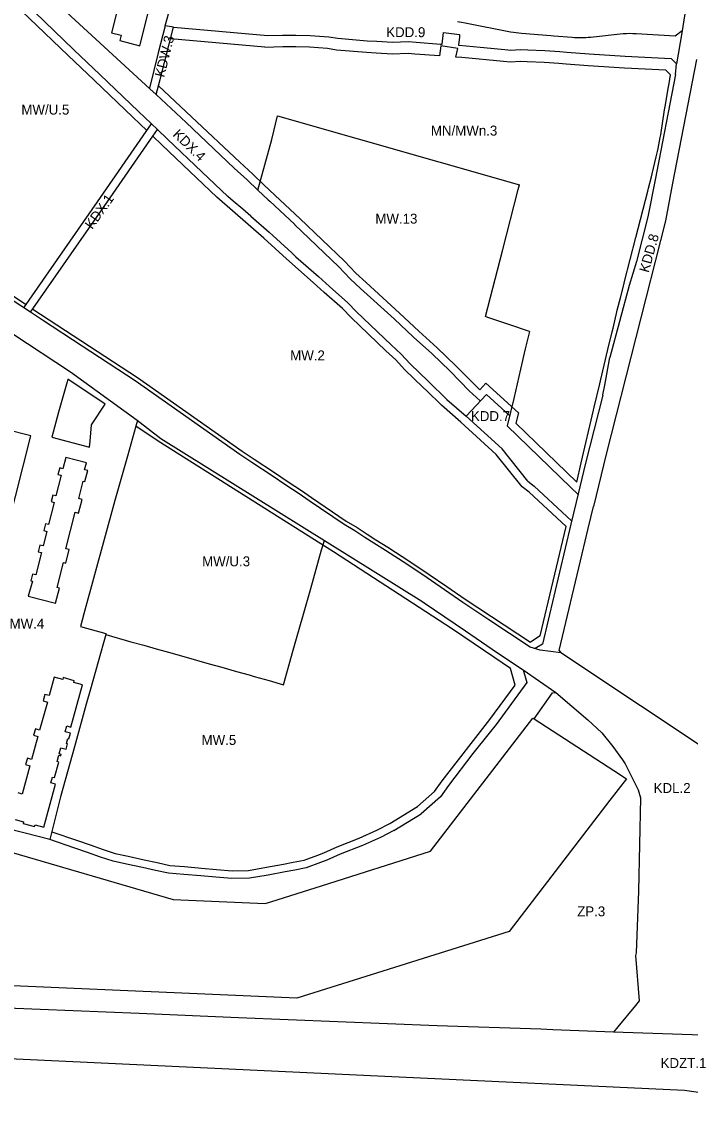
# Model space of a CAD drawing. Extents: x 7427060 to 7429122, y 5545301 to 5546237.
# Drawn here: x 7427447 to 7427783, y 5545402 to 5545952 of the extents above; entities that cross this region are included whole.
import ezdxf

# ---------------------------------------------------------------- set-up
doc = ezdxf.new("R2010")
doc.units = 0
for name, color, linetype in [('LIN_Linia Zabudowy Nieprzekraczalna', 7, 'Continuous'), ('LIN_Linia Zabudowy Obowiązujaca', 7, 'Continuous'), ('LIN_Linie Rozgraniczajace', 7, 'Continuous'), ('TXT_Oznaczenia Przeznaczenia', 7, 'Continuous')]:
    doc.layers.add(name, color=color, linetype=linetype)

msp = doc.modelspace()

# ---------------------------------------------------------------- linework, layer by layer
at = {"layer": 'LIN_Linia Zabudowy Nieprzekraczalna'}
for p, q in [((7427515.49, 5545919.37), (7427532.17, 5545903.75)), ((7427532.17, 5545903.75), (7427556.34, 5545880.88)), ((7427556.34, 5545880.88), (7427562.91, 5545874.92)), ((7427562.91, 5545874.92), (7427568.26, 5545869.74)), ((7427568.26, 5545869.74), (7427574.2, 5545864.16)), ((7427574.2, 5545864.16), (7427586.61, 5545852.55)), ((7427586.61, 5545852.55), (7427609.05, 5545831.07)), ((7427609.05, 5545831.07), (7427614.75, 5545825.05)), ((7427614.75, 5545825.05), (7427619.94, 5545820.27)), ((7427619.94, 5545820.27), (7427636.75, 5545804.98)), ((7427608.08, 5545807.21), (7427598.93, 5545815.39)), ((7427612.39, 5545802.7), (7427608.08, 5545807.21)), ((7427629.84, 5545786.01), (7427612.39, 5545802.7)), ((7427636.75, 5545804.98), (7427646.54, 5545795.79)), ((7427646.54, 5545795.79), (7427655.77, 5545787.49)), ((7427634.87, 5545781.46), (7427629.84, 5545786.01)), ((7427655.77, 5545787.49), (7427665.1, 5545778.47)), ((7427639.3, 5545776.6), (7427634.87, 5545781.46)), ((7427648.65, 5545767.57), (7427639.3, 5545776.6)), ((7427665.1, 5545778.47), (7427677.17, 5545766.24)), ((7427469.81, 5545771.76), (7427469.43, 5545770.37)), ((7427488.62, 5545759.04), (7427469.81, 5545771.76)), ((7427677.17, 5545766.24), (7427680.32, 5545769.63)), ((7427680.32, 5545769.63), (7427696.63, 5545754.74)), ((7427650.32, 5545765.95), (7427648.65, 5545767.57)), ((7427728.18, 5545729.5), (7427734.47, 5545756.06)), ((7427695.36, 5545749.49), (7427726.04, 5545719.83)), ((7427698.51, 5545717.41), (7427685.46, 5545733.8)), ((7427726.04, 5545719.83), (7427728.18, 5545729.5)), ((7427580.71, 5545720.05), (7427587.45, 5545715.57)), ((7427587.45, 5545715.57), (7427592.52, 5545712.1)), ((7427592.52, 5545712.1), (7427610, 5545700.26)), ((7427610, 5545700.26), (7427615.41, 5545696.96)), ((7427615.41, 5545696.96), (7427620.51, 5545693.64)), ((7427620.51, 5545693.64), (7427624.94, 5545690.74)), ((7427624.94, 5545690.74), (7427630.88, 5545687.17)), ((7427630.88, 5545687.17), (7427642.06, 5545679.91)), ((7427642.06, 5545679.91), (7427651.77, 5545673.3)), ((7427651.77, 5545673.3), (7427660.6, 5545667.34)), ((7427660.6, 5545667.34), (7427669.87, 5545660.87)), ((7427669.87, 5545660.87), (7427702.66, 5545639.22)), ((7427707.61, 5545642.4), (7427702.66, 5545639.22))]:
    msp.add_line(p, q, dxfattribs=at)
for points in [[(7427509.67, 5545896.86), (7427502.61, 5545903.62), (7427483.14, 5545922.22), (7427470.05, 5545934.63), (7427450.43, 5545953.5), (7427437, 5545966.33), (7427424.67, 5545986.01), (7427416.22, 5545999.42)], [(7427569.03, 5545938.78), (7427521.48, 5545943.06)], [(7427656.98, 5545934.44), (7427644.55, 5545935.32), (7427641.1, 5545935.72), (7427633.25, 5545935.32), (7427625.1, 5545935.81), (7427620.13, 5545936.08), (7427605.11, 5545937.4), (7427600.49, 5545938.09), (7427591.51, 5545938.78), (7427584.53, 5545938.94), (7427581.53, 5545938.93), (7427578.01, 5545938.93), (7427568.99, 5545938.63)], [(7427665.18, 5545933.85), (7427666.11, 5545938.13), (7427657.56, 5545939.58), (7427656.98, 5545934.44)], [(7427668.16, 5545933.64), (7427665.18, 5545933.85)], [(7427773.16, 5545924.96), (7427770.94, 5545927.19), (7427750, 5545928.3), (7427731.84, 5545929.51), (7427720.66, 5545930.34), (7427717.01, 5545930.61), (7427709.62, 5545931.14), (7427701.1, 5545931.43), (7427697.58, 5545931.59), (7427692.73, 5545931.25), (7427689.15, 5545931.65), (7427668.16, 5545933.64)], [(7427734.47, 5545756.06), (7427734.8, 5545757.52), (7427737.6, 5545769.35), (7427738, 5545770.91), (7427741.72, 5545786.63), (7427742.05, 5545788.11), (7427743.47, 5545794.03), (7427743.87, 5545795.59), (7427744.27, 5545797.34), (7427744.65, 5545798.88), (7427746.04, 5545804.75), (7427746.44, 5545806.35), (7427747.96, 5545812.58), (7427749.64, 5545819.22), (7427750.07, 5545820.79), (7427755.78, 5545843.02), (7427761.75, 5545866.33), (7427762.15, 5545867.85), (7427763.57, 5545873.52), (7427764.01, 5545875.13), (7427766.06, 5545883.58), (7427766.65, 5545886.37), (7427766.96, 5545887.85), (7427767.96, 5545893.3), (7427768.27, 5545894.73), (7427770.27, 5545907.32), (7427770.56, 5545908.99), (7427772.19, 5545918.91), (7427772.46, 5545920.46), (7427773.16, 5545924.96)], [(7427544.8, 5545863.39), (7427534.59, 5545873.11), (7427517.24, 5545889.61), (7427512.59, 5545894.06)], [(7427352.42, 5545872.18), (7427414.39, 5545831.76), (7427422.77, 5545826.42), (7427448.9, 5545809.21)], [(7427598.93, 5545815.39), (7427593.39, 5545820.35), (7427579.84, 5545832.24), (7427568.5, 5545842.71), (7427544.8, 5545863.39)], [(7427452.24, 5545807), (7427504.85, 5545772.52), (7427557.56, 5545735.42), (7427563.62, 5545731.4), (7427573.79, 5545724.65), (7427580.71, 5545720.05)], [(7427469.43, 5545770.37), (7427465.2, 5545755.15), (7427461.71, 5545742.41), (7427480.77, 5545737.44), (7427481.01, 5545740.42), (7427481.79, 5545748.67), (7427488.62, 5545759.04)], [(7427685.46, 5545733.8), (7427667.67, 5545750.03), (7427657.93, 5545758.56), (7427650.32, 5545765.95)], [(7427696.63, 5545754.74), (7427695.36, 5545749.49)], [(7427653.4, 5545652.36), (7427603.49, 5545684.74), (7427515.39, 5545740.53), (7427504.08, 5545747.95)], [(7427720.68, 5545697.46), (7427702.08, 5545714.73), (7427698.51, 5545717.41)], [(7427707.61, 5545642.4), (7427720.68, 5545697.46)], [(7427692.68, 5545626.03), (7427684.35, 5545631.78), (7427663.51, 5545645.76), (7427653.4, 5545652.36)], [(7427695.01, 5545617.71), (7427692.68, 5545626.03)], [(7427461.71, 5545543.77), (7427474.68, 5545539.42), (7427481.04, 5545537.2), (7427487.62, 5545534.89), (7427493.67, 5545532.9), (7427500.14, 5545531.5), (7427508.25, 5545529.73), (7427514.75, 5545528.31), (7427521.19, 5545526.91), (7427528.53, 5545526.29), (7427537.08, 5545525.55), (7427544.62, 5545524.91), (7427552.54, 5545524.22), (7427560.83, 5545524.4), (7427569.91, 5545525.96), (7427578.47, 5545527.51), (7427583.35, 5545528.47), (7427588.76, 5545529.52), (7427595.65, 5545532.04), (7427598.64, 5545533.14), (7427605.4, 5545536.22), (7427616.54, 5545540.62), (7427625.42, 5545544.58), (7427631.91, 5545547.97), (7427645.85, 5545556.53), (7427654.35, 5545564.14), (7427658.21, 5545569.53), (7427682.27, 5545600.28), (7427695.01, 5545617.71)]]:
    msp.add_lwpolyline(points, dxfattribs=at)
at = {"layer": 'LIN_Linia Zabudowy Obowiązujaca'}
for points in [[(7427508.23, 5546015.36), (7427508.7, 5546013.27), (7427505.68, 5546001.27), (7427491.76, 5545946.04), (7427496.67, 5545944.79), (7427496.01, 5545942.12), (7427506.07, 5545939.57), (7427510.61, 5545957.48), (7427509.6, 5545957.75), (7427510.26, 5545960.36), (7427510.96, 5545963.11), (7427511.97, 5545962.85), (7427516.31, 5545980.2), (7427517.92, 5545986.57), (7427519.54, 5545992.99), (7427520.67, 5545997.46), (7427520.82, 5545997.96), (7427519.77, 5545998.23), (7427520.45, 5546000.84), (7427521.19, 5546003.58), (7427522.17, 5546003.34), (7427524.44, 5546012.33), (7427515.23, 5546014.57), (7427514.52, 5546016.56)], [(7427443.37, 5545550), (7427447.6, 5545548.85), (7427447.37, 5545548), (7427453.07, 5545546.44), (7427453.32, 5545547.34), (7427457.69, 5545546.15), (7427463.6, 5545567.77), (7427461.28, 5545568.4), (7427462.1, 5545571.39), (7427463.2, 5545571.09), (7427465.35, 5545578.95), (7427464.48, 5545579.19), (7427465.34, 5545582.32), (7427466.3, 5545582.06), (7427466.49, 5545582.73), (7427465.52, 5545583), (7427466.37, 5545586.08), (7427468.98, 5545585.37), (7427469.72, 5545588.07), (7427469.14, 5545588.23), (7427469.82, 5545590.74), (7427470.37, 5545590.59), (7427471.14, 5545593.4), (7427468.54, 5545594.11), (7427469.35, 5545597.08), (7427471.38, 5545596.53), (7427477.2, 5545617.83), (7427472.86, 5545619.01), (7427473.09, 5545619.88), (7427467.5, 5545621.41), (7427467.26, 5545620.54), (7427462.97, 5545621.71), (7427460.41, 5545612.35), (7427458.29, 5545612.93), (7427457.41, 5545609.72), (7427459.53, 5545609.14), (7427455.66, 5545594.98), (7427453.48, 5545595.57), (7427452.62, 5545592.43), (7427454.8, 5545591.83), (7427451.63, 5545580.21), (7427449.48, 5545580.8), (7427448.61, 5545577.64), (7427450.76, 5545577.05), (7427446.87, 5545562.79), (7427444.76, 5545563.37)]]:
    msp.add_lwpolyline(points, dxfattribs=at)
for points in [[(7427418.42, 5545670.22), (7427431.7, 5545666.82), (7427451.28, 5545743.12), (7427438.02, 5545746.53)], [(7427479.19, 5545729.55), (7427468.82, 5545732.19), (7427467.31, 5545726.6), (7427465.74, 5545727.02), (7427464.85, 5545723.71), (7427466.48, 5545723.29), (7427463.88, 5545712.96), (7427462.24, 5545713.33), (7427461.38, 5545710.04), (7427463.02, 5545709.65), (7427460.14, 5545698.45), (7427458.56, 5545698.81), (7427457.7, 5545695.52), (7427459.28, 5545695.07), (7427457.39, 5545687.7), (7427455.82, 5545688.05), (7427454.95, 5545684.76), (7427456.52, 5545684.35), (7427453.73, 5545673.13), (7427452.13, 5545673.51), (7427451.25, 5545670.23), (7427451.98, 5545670.03), (7427449.95, 5545662.45), (7427463.71, 5545658.93), (7427465.63, 5545666.42), (7427464.46, 5545666.72), (7427467.66, 5545679.31), (7427468.83, 5545679.01), (7427470.58, 5545685.89), (7427468.83, 5545686.34), (7427473.52, 5545704.73), (7427475.26, 5545704.29), (7427477.02, 5545711.14), (7427475.3, 5545711.58), (7427477.54, 5545720.41), (7427478.4, 5545720.2), (7427479.85, 5545725.67), (7427478.31, 5545726.02)]]:
    msp.add_lwpolyline(points, close=True, dxfattribs=at)
at = {"layer": 'LIN_Linie Rozgraniczajace'}
for p, q in [((7427518.85, 5545949.52), (7427522.48, 5545962.91)), ((7427522.97, 5545948.95), (7427518.85, 5545949.52)), ((7427778.85, 5545946.12), (7427776.24, 5545930.38)), ((7427775.67, 5545925.14), (7427776.24, 5545930.38)), ((7427509.3, 5545896.34), (7427511.98, 5545900.19)), ((7427484.77, 5545860.95), (7427509.3, 5545896.34)), ((7427447.76, 5545807.56), (7427484.77, 5545860.95)), ((7427670.34, 5545753.01), (7427680.55, 5545764)), ((7427701.32, 5545720.3), (7427688.39, 5545736.54)), ((7427723.04, 5545717.16), (7427726.65, 5545713.68)), ((7427597.58, 5545685.72), (7427599.05, 5545690.47)), ((7427708.7, 5545638.35), (7427705.12, 5545636.05)), ((7427717.19, 5545635.14), (7427718, 5545633.88)), ((7427742.75, 5545559.75), (7427691.96, 5545493.61)), ((7427633.88, 5545544.49), (7427647.78, 5545552.9)), ((7427422.46, 5545538.97), (7427522.78, 5545509.77)), ((7427585.14, 5545459.97), (7427206.59, 5545476.7)), ((7427746.69, 5545445.54), (7427744.57, 5545442.93))]:
    msp.add_line(p, q, dxfattribs=at)
for points in [[(7427565.5, 5545866.85), (7427560.18, 5545872), (7427553.62, 5545877.94), (7427529.43, 5545900.84), (7427514.37, 5545914.94), (7427511.16, 5545917.88), (7427469.3, 5545956.34), (7427456.33, 5545968.26), (7427443.51, 5545981.95), (7427427.27, 5546009.82)], [(7427550.41, 5545863.58), (7427537.35, 5545876.01), (7427520, 5545892.5), (7427514.9, 5545897.39), (7427505.38, 5545906.51), (7427485.9, 5545925.12), (7427472.81, 5545937.52), (7427453.2, 5545956.39), (7427440.12, 5545968.88), (7427428.06, 5545988.14), (7427416.8, 5546006)], [(7427780.43, 5545955.6), (7427778.85, 5545946.12)], [(7427518.85, 5545949.52), (7427515.37, 5545935.93), (7427510.89, 5545918.13)], [(7427666.05, 5545951.74), (7427667.92, 5545951.47), (7427669.79, 5545951.14), (7427692.74, 5545946.63), (7427694.11, 5545946.38), (7427695.48, 5545946.17), (7427696.86, 5545946), (7427698.25, 5545945.87), (7427712.96, 5545944.68), (7427714.45, 5545944.56), (7427723.72, 5545943.81), (7427724.87, 5545943.73), (7427726.02, 5545943.68), (7427727.18, 5545943.65), (7427728.34, 5545943.66), (7427729.49, 5545943.69), (7427730.65, 5545943.74), (7427731.8, 5545943.83), (7427732.95, 5545943.94), (7427749.39, 5545945.7), (7427751.02, 5545945.78), (7427752.64, 5545945.81), (7427754.25, 5545945.79), (7427755.86, 5545945.71), (7427775.55, 5545944.5), (7427779.04, 5545947.27)], [(7427514.37, 5545914.94), (7427516.3, 5545922.58), (7427522.97, 5545948.95)], [(7427522.97, 5545948.95), (7427570.44, 5545944.68), (7427577.91, 5545944.93), (7427580.12, 5545944.93), (7427581.52, 5545944.93), (7427584.59, 5545944.94), (7427591.81, 5545944.77), (7427601.16, 5545944.06), (7427605.82, 5545943.36), (7427620.56, 5545942.07), (7427625.45, 5545941.8), (7427633.28, 5545941.33), (7427641.29, 5545941.74), (7427645.11, 5545941.3), (7427657.41, 5545940.42), (7427658.19, 5545940.38), (7427658.99, 5545946.15), (7427666.99, 5545945.19)], [(7427666.99, 5545945.19), (7427666.98, 5545943.96), (7427666.48, 5545939.9), (7427666.75, 5545939.88), (7427677.39, 5545938.79), (7427689.77, 5545937.62), (7427692.86, 5545937.27), (7427697.5, 5545937.6), (7427701.34, 5545937.43), (7427709.94, 5545937.13), (7427717.45, 5545936.59), (7427721.1, 5545936.32), (7427732.26, 5545935.5), (7427750.36, 5545934.29), (7427773.56, 5545933.06), (7427776.24, 5545930.38)], [(7427206.38, 5545936.07), (7427206.36, 5545914.88), (7427207.15, 5545859.14), (7427207.2, 5545825.05), (7427206.65, 5545803.79), (7427202.76, 5545754.61), (7427190.08, 5545647.92), (7427181.06, 5545573.67), (7427163.56, 5545439.73), (7427415.14, 5545430.84), (7427629.43, 5545420.86), (7427780.19, 5545413.81), (7427861.1, 5545402.15)], [(7427503.73, 5545770.87), (7427476.98, 5545788.24), (7427457.14, 5545801.37), (7427451.1, 5545805.36), (7427436.95, 5545814.7), (7427421.68, 5545824.74), (7427413.31, 5545830.08), (7427410.1, 5545832.16), (7427387.82, 5545846.64), (7427376.42, 5545854.14), (7427370.41, 5545858.09), (7427353.59, 5545869.02), (7427351.35, 5545870.49), (7427345.54, 5545874.34), (7427311.72, 5545896.51), (7427289.56, 5545910.99), (7427269.82, 5545924.14), (7427250.42, 5545937.82)], [(7427786.27, 5545932.57), (7427774.26, 5545870.28), (7427770.61, 5545851.37)], [(7427775.67, 5545925.14), (7427765.42, 5545871.98), (7427761.82, 5545853.33), (7427756.15, 5545830.93)], [(7427565.5, 5545866.85), (7427572.55, 5545892.28), (7427575.43, 5545904.29)], [(7427575.43, 5545904.29), (7427697.23, 5545869.54)], [(7427451.1, 5545805.36), (7427488.06, 5545858.67), (7427512.59, 5545894.06), (7427514.9, 5545897.39)], [(7427565.5, 5545866.85), (7427570.64, 5545862.02), (7427571.46, 5545861.24), (7427583.86, 5545849.64), (7427583.99, 5545849.51), (7427606.21, 5545828.25), (7427611.94, 5545822.2), (7427617.24, 5545817.32), (7427634.03, 5545802.04), (7427643.83, 5545792.84), (7427653.04, 5545784.56), (7427662.29, 5545775.63), (7427671.94, 5545765.85), (7427677.48, 5545760.7)], [(7427702.17, 5545795.69), (7427691.89, 5545799.14), (7427681.28, 5545802.69), (7427680.1, 5545803.23), (7427688.56, 5545836.21), (7427696.6, 5545867.13), (7427697.23, 5545869.54)], [(7427561.88, 5545853.8), (7427557.96, 5545857.22), (7427553.11, 5545861.31), (7427550.41, 5545863.58)], [(7427561.88, 5545853.8), (7427571.17, 5545845.69), (7427582.52, 5545835.21), (7427584.65, 5545833.34), (7427596.04, 5545823.34), (7427601.6, 5545818.37), (7427610.86, 5545810.09), (7427615.22, 5545805.53), (7427632.56, 5545788.94), (7427637.7, 5545784.3), (7427642.17, 5545779.39), (7427651.43, 5545770.44), (7427660.64, 5545761.5), (7427670.34, 5545753.01), (7427688.39, 5545736.54)], [(7427770.61, 5545851.37), (7427740.83, 5545733.92), (7427734.45, 5545707.62)], [(7427756.15, 5545830.93), (7427752.42, 5545818.89), (7427742.66, 5545782.66)], [(7427702.17, 5545795.69), (7427700.12, 5545787.01), (7427697.69, 5545776.75), (7427694.27, 5545762), (7427690.93, 5545748.21)], [(7427442.15, 5545794.5), (7427471.16, 5545775.4), (7427504.66, 5545751.1), (7427516.72, 5545741.81), (7427648.03, 5545659.93), (7427649.2, 5545659.16), (7427670.02, 5545644.98), (7427686.15, 5545633.93), (7427699.09, 5545625.39), (7427715.54, 5545613.93), (7427731.54, 5545600.2), (7427738.56, 5545593.62), (7427744.25, 5545586.78), (7427749.02, 5545580.03), (7427750.47, 5545577.97), (7427756.89, 5545564.96), (7427758.19, 5545560.85), (7427757.18, 5545513.98), (7427755.9, 5545482.8), (7427755.66, 5545481.49), (7427757.38, 5545458.7), (7427755.52, 5545456.41), (7427746.69, 5545445.54)], [(7427739.08, 5545763.59), (7427739.11, 5545763.75), (7427740.16, 5545768.65), (7427742.66, 5545782.66)], [(7427586.33, 5545713.91), (7427579.6, 5545718.38), (7427572.68, 5545722.98), (7427562.51, 5545729.73), (7427556.43, 5545733.77), (7427503.73, 5545770.87)], [(7427680.55, 5545764), (7427692.18, 5545753.38)], [(7427739.08, 5545763.59), (7427730.43, 5545729.46), (7427725.7, 5545709.73)], [(7427504.91, 5545750.91), (7427504.08, 5545747.95), (7427499.87, 5545732.96), (7427493.57, 5545710.68), (7427477.94, 5545653.54), (7427476.24, 5545647.2), (7427488.99, 5545643.56), (7427488.95, 5545643.07)], [(7427690.93, 5545748.21), (7427723.04, 5545717.16)], [(7427701.32, 5545720.3), (7427704.65, 5545717.8), (7427723.43, 5545700.36)], [(7427591.4, 5545710.45), (7427589.59, 5545711.69), (7427586.33, 5545713.91)], [(7427859.75, 5545613.18), (7427843.8, 5545604.43), (7427799.57, 5545580.14), (7427798.29, 5545580.52), (7427718, 5545633.88), (7427707.59, 5545635.27), (7427702.63, 5545636.84), (7427681.7, 5545650.45), (7427668.75, 5545659.22), (7427659.47, 5545665.69), (7427650.65, 5545671.64), (7427640.95, 5545678.24), (7427629.82, 5545685.47), (7427623.88, 5545689.05), (7427619.42, 5545691.96), (7427614.34, 5545695.27), (7427608.92, 5545698.58), (7427591.4, 5545710.45)], [(7427725.7, 5545709.73), (7427723.01, 5545698.63), (7427708.7, 5545638.35)], [(7427717.19, 5545635.14), (7427728.68, 5545683.82), (7427731.76, 5545696.53), (7427734.45, 5545707.62)], [(7427578.4, 5545617.88), (7427583.33, 5545635.17), (7427591.52, 5545663.98), (7427592.2, 5545666.35), (7427597.58, 5545685.72)], [(7427488.95, 5545643.07), (7427481.25, 5545615.62), (7427479.14, 5545608.11), (7427473.12, 5545586.61), (7427466.2, 5545561.49), (7427460.72, 5545539.88)], [(7427488.95, 5545643.07), (7427501.59, 5545639.51), (7427508.04, 5545637.69), (7427514.29, 5545635.93), (7427520.55, 5545634.17), (7427527.1, 5545632.33), (7427534.6, 5545630.21), (7427541, 5545628.41), (7427547.32, 5545626.63), (7427554.82, 5545624.52), (7427561.06, 5545622.76), (7427563.67, 5545622.02), (7427571.17, 5545619.92), (7427578.4, 5545617.88)], [(7427699.09, 5545625.39), (7427700.89, 5545618.97), (7427685.46, 5545597.87), (7427681.87, 5545593.42), (7427673.63, 5545583.21), (7427661.41, 5545567.13), (7427657.35, 5545561.45), (7427647.78, 5545552.9)], [(7427522.78, 5545509.77), (7427569.23, 5545507.71), (7427572.57, 5545508.77), (7427597.5, 5545516.66), (7427652.42, 5545534.05), (7427703.88, 5545601.08), (7427704.62, 5545600.6), (7427713.8, 5545613.7), (7427715.54, 5545613.93)], [(7427704.62, 5545600.6), (7427744.69, 5545574.65), (7427751.03, 5545570.54), (7427742.75, 5545559.75)], [(7427448.4, 5545543.04), (7427442.24, 5545544.7), (7427429.65, 5545545.83)], [(7427633.88, 5545544.49), (7427627.16, 5545540.98), (7427618.09, 5545536.93), (7427606.96, 5545532.54), (7427603.56, 5545530.99), (7427600.18, 5545529.45), (7427597.03, 5545528.29), (7427589.84, 5545525.65), (7427584.11, 5545524.54), (7427579.21, 5545523.58), (7427570.6, 5545522.02), (7427561.21, 5545520.41), (7427552.41, 5545520.22), (7427544.28, 5545520.92), (7427536.74, 5545521.56), (7427528.19, 5545522.3), (7427520.59, 5545522.95), (7427513.9, 5545524.4), (7427507.4, 5545525.82), (7427499.29, 5545527.59), (7427492.62, 5545529.04), (7427486.34, 5545531.1), (7427479.72, 5545533.42), (7427473.38, 5545535.64), (7427460.72, 5545539.88), (7427448.4, 5545543.04)], [(7427691.96, 5545493.61), (7427599.62, 5545464.53), (7427585.14, 5545459.97)], [(7427744.57, 5545442.93), (7427713.99, 5545444.18), (7427707.91, 5545444.43), (7427655.72, 5545446.06), (7427605.76, 5545448.17), (7427555.68, 5545450.21), (7427505.83, 5545452.26), (7427455.88, 5545454.34), (7427406.01, 5545456.38), (7427355.95, 5545458.17), (7427348.42, 5545458.9), (7427328.81, 5545460.79), (7427302.55, 5545462.38), (7427259.67, 5545467.06), (7427167.7, 5545471.41)], [(7427808.75, 5545440.81), (7427744.57, 5545442.93)]]:
    msp.add_lwpolyline(points, dxfattribs=at)

# ---------------------------------------------------------------- texts
at = {"layer": 'TXT_Oznaczenia Przeznaczenia'}
for s, rotation, p in [('KDW.3', 76.1215, (7427518.35, 5545923.35)), ('KDX.4', 315.8808, (7427522.34, 5545894.44)), ('KDX.1', 54.5373, (7427482.09, 5545846.8)), ('KDD.8', 74.3513, (7427762.18, 5545825.02)), ('MW.2', 360, (7427581.77, 5545781.14)), ('MW/U.3', 360, (7427537.44, 5545677.46)), ('MW.4', 360, (7427440.5, 5545646.07)), ('MW.5', 360, (7427537.16, 5545587.55)), ('KDL.2', 360, (7427764.74, 5545563.37)), ('ZP.3', 360, (7427726.23, 5545501.26)), ('KDZT.1', 360, (7427768.24, 5545424.9))]:
    msp.add_text(s, height=5, rotation=rotation, dxfattribs=at).set_placement(p)
for s, p in [('KDD.9', (7427630.11, 5545943.87)), ('MW/U.5', (7427446.45, 5545904.88)), ('MN/MWn.3', (7427652.6, 5545894.34)), ('MW.13', (7427624.64, 5545850)), ('KDD.7', (7427672.76, 5545750.6))]:
    msp.add_text(s, height=5, dxfattribs=at).set_placement(p)

doc.saveas('drawing.dxf')
